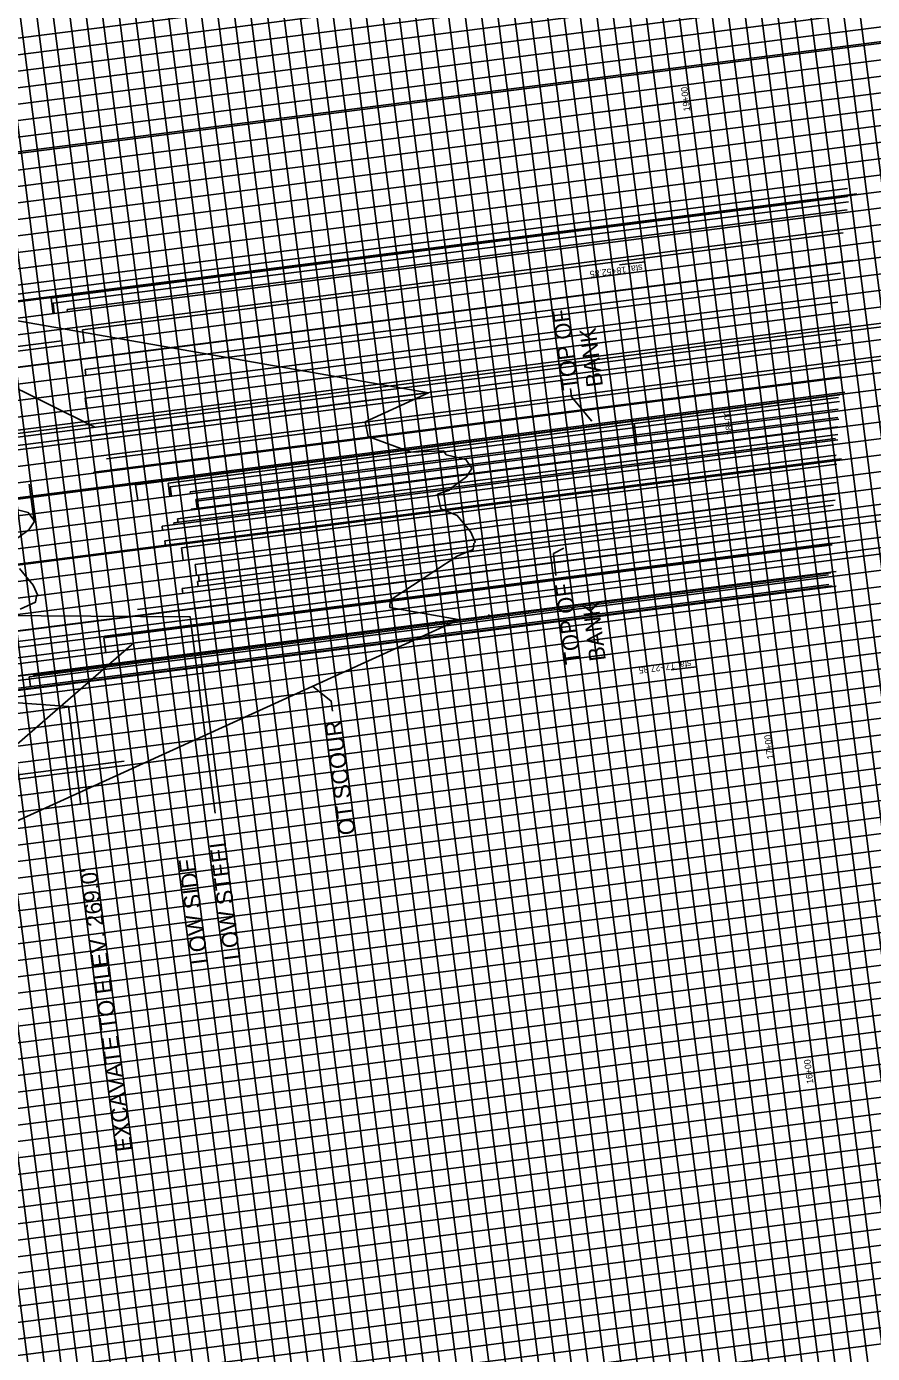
# Model space of a CAD drawing. Extents: x 2166991 to 2168413, y 842679 to 844296.
# Drawn here: x 2167837.4 to 2168096.3, y 843150.5 to 843556.7 of the extents above; entities that cross this region are included whole.
import ezdxf

# ---------------------------------------------------------------- set-up
doc = ezdxf.new("R2010")
doc.units = 0
for name, color, linetype in [('Exist Vertical Profile Ground Line', 7, 'Continuous'), ('Old_Level_46', 7, 'Continuous'), ('Prop Drainage Structure Bridge', 7, 'Continuous'), ('Prop Hydrographic Scour Overtopping', 7, 'Continuous'), ('Prop Plan Preparation Drainage Notes Label', 7, 'Continuous'), ('Prop Plan Preparation Sheet Bridge Report Limited Study CELL', 7, 'Continuous'), ('Scratch_Level_2', 7, 'Continuous'), ('Scratch_Level_3', 7, 'Continuous'), ('Scratch_Level_4', 7, 'Continuous'), ('Scratch_Level_8', 7, 'Continuous'), ('Scratch_Level_9', 7, 'Continuous')]:
    doc.layers.add(name, color=color, linetype=linetype)

msp = doc.modelspace()

# ---------------------------------------------------------------- linework, layer by layer
at = {"layer": 'Exist Vertical Profile Ground Line'}
for points in [[(2167834.04, 843399.62), (2167838.15, 843402.55), (2167839.75, 843405.06), (2167839.63, 843405.57), (2167837.93, 843407.87), (2167831.79, 843409.39)], [(2167835.45, 843378.32), (2167840.17, 843380.47), (2167840.43, 843382.37), (2167840.86, 843382.52), (2167839.45, 843385.69), (2167835.28, 843390.74)]]:
    msp.add_lwpolyline(points, dxfattribs=at)
at = {"layer": 'Old_Level_46'}
msp.add_line((2168024.22, 843428.68), (2168023.37, 843435.3), dxfattribs=at)
for points in [[(2168003.85, 843445.87), (2168004.17, 843443.36), (2168010.37, 843435.83)], [(2168001.8, 843397), (2167998.64, 843395.31), (2167999.43, 843388.63)], [(2167931.04, 843347.13), (2167930.65, 843350.18), (2167924.9, 843354.74)]]:
    msp.add_lwpolyline(points, dxfattribs=at)
at = {"layer": 'Prop Drainage Structure Bridge'}
for p, q in [((2167794.54, 843453.55), (2167848.25, 843460.41)), ((2167765.91, 843419.65), (2167960.44, 843444.5)), ((2167768.38, 843349.4), (2167969.63, 843375.1)), ((2167821.41, 843325.93), (2167864.73, 843331.46)), ((2167848.71, 843329.41), (2167867.3, 843331.79))]:
    msp.add_line(p, q, dxfattribs=at)
at = {"layer": 'Prop Hydrographic Scour Overtopping'}
for p, q in [((2167960.44, 843444.56), (2167801.84, 843472.35)), ((2167960.44, 843444.5), (2167941.02, 843435.65)), ((2167839.73, 843405.14), (2167838.27, 843416.61)), ((2167969.55, 843375.15), (2167948.63, 843378.82)), ((2167969.56, 843375.09), (2167815.18, 843304.73)), ((2167963.34, 843374.3), (2167962.46, 843374.35))]:
    msp.add_line(p, q, dxfattribs=at)
for points in [[(2167948.63, 843378.82), (2167948.71, 843381.1), (2167969.2, 843394.49), (2167974.08, 843396.56), (2167974.3, 843398.45), (2167974.74, 843398.81), (2167973.35, 843401.92), (2167969.17, 843406.97), (2167964.22, 843409.05), (2167963.2, 843413.51), (2167966.87, 843414.7), (2167967.84, 843415.74), (2167972.1, 843418.87), (2167973.54, 843421.14), (2167973.6, 843421.6), (2167971.82, 843424.1), (2167965.87, 843425.58), (2167965.04, 843426.75), (2167955.02, 843426.33), (2167942.01, 843431.12), (2167941.02, 843435.65)], [(2167978.91, 843376.29), (2167978.87, 843376.63)], [(2167915.33, 843361.79), (2167914.99, 843361.71)]]:
    msp.add_lwpolyline(points, dxfattribs=at)
at = {"layer": 'Prop Plan Preparation Drainage Notes Label'}
for points in [[(2167895.15, 843315.83), (2167893.14, 843331.53), (2167887.44, 843375.99), (2167781.12, 843376.66)], [(2167854.04, 843318.38), (2167850.29, 843348.53), (2167813.82, 843351.12)]]:
    msp.add_lwpolyline(points, dxfattribs=at)
at = {"layer": 'Prop Plan Preparation Sheet Bridge Report Limited Study CELL'}
for p, q in [((2168181.94, 842821.17), (2168023.56, 844061.1)), ((2168132.34, 842814.84), (2167973.96, 844054.76)), ((2168082.74, 842808.5), (2167924.37, 844048.43)), ((2168033.15, 842802.17), (2167874.77, 844042.09)), ((2167983.55, 842795.83), (2167825.17, 844035.76)), ((2168168.85, 842844.7), (2168016.81, 844035.03)), ((2168173.81, 842845.34), (2168021.77, 844035.67)), ((2168183.73, 842846.6), (2168031.69, 844036.93)), ((2168134.13, 842840.27), (2167982.09, 844030.6)), ((2168139.09, 842840.9), (2167987.05, 844031.23)), ((2168144.05, 842841.54), (2167992.01, 844031.86)), ((2168149.01, 842842.17), (2167996.97, 844032.5)), ((2168153.97, 842842.8), (2168001.93, 844033.13)), ((2168158.93, 842843.44), (2168006.89, 844033.77)), ((2168163.89, 842844.07), (2168011.85, 844034.4)), ((2167933.95, 842789.5), (2167775.57, 844029.42)), ((2168104.37, 842836.47), (2167952.33, 844026.8)), ((2168109.33, 842837.1), (2167957.29, 844027.43)), ((2168114.29, 842837.73), (2167962.25, 844028.06)), ((2168119.25, 842838.37), (2167967.21, 844028.7)), ((2168124.21, 842839), (2167972.17, 844029.33)), ((2167884.35, 842783.16), (2167725.98, 844023.09)), ((2168074.61, 842832.67), (2167922.57, 844023)), ((2168084.53, 842833.93), (2167932.49, 844024.26)), ((2168089.49, 842834.57), (2167937.45, 844024.9)), ((2168094.45, 842835.2), (2167942.41, 844025.53)), ((2168099.41, 842835.83), (2167947.37, 844026.16)), ((2168039.9, 842828.23), (2167887.86, 844018.56)), ((2168044.86, 842828.87), (2167892.82, 844019.19)), ((2168049.82, 842829.5), (2167897.78, 844019.83)), ((2168054.78, 842830.13), (2167902.74, 844020.46)), ((2168059.74, 842830.77), (2167907.69, 844021.1)), ((2168064.7, 842831.4), (2167912.65, 844021.73)), ((2168069.66, 842832.03), (2167917.61, 844022.36)), ((2168010.14, 842824.43), (2167858.1, 844014.76)), ((2168015.1, 842825.06), (2167863.06, 844015.39)), ((2168020.06, 842825.7), (2167868.02, 844016.03)), ((2168025.02, 842826.33), (2167872.98, 844016.66)), ((2168034.94, 842827.6), (2167882.9, 844017.93)), ((2167975.42, 842820), (2167823.38, 844010.33)), ((2167985.34, 842821.26), (2167833.3, 844011.59)), ((2167990.3, 842821.9), (2167838.26, 844012.23)), ((2167995.26, 842822.53), (2167843.22, 844012.86)), ((2168000.22, 842823.16), (2167848.18, 844013.49)), ((2168005.18, 842823.8), (2167853.14, 844014.13)), ((2167945.66, 842816.2), (2167793.62, 844006.52)), ((2167950.62, 842816.83), (2167798.58, 844007.16)), ((2167955.58, 842817.46), (2167803.54, 844007.79)), ((2167960.54, 842818.1), (2167808.5, 844008.43)), ((2167965.5, 842818.73), (2167813.46, 844009.06)), ((2167970.46, 842819.36), (2167818.42, 844009.69)), ((2167910.94, 842811.76), (2167758.9, 844002.09)), ((2167915.9, 842812.39), (2167763.86, 844002.72)), ((2167920.86, 842813.03), (2167768.82, 844003.36)), ((2167925.82, 842813.66), (2167773.78, 844003.99)), ((2167935.74, 842814.93), (2167783.7, 844005.26)), ((2167940.7, 842815.56), (2167788.66, 844005.89)), ((2167886.15, 842808.59), (2167734.11, 843998.92)), ((2167891.11, 842809.23), (2167739.06, 843999.56)), ((2167896.07, 842809.86), (2167744.02, 844000.19)), ((2167901.03, 842810.49), (2167748.98, 844000.82)), ((2167905.98, 842811.13), (2167753.94, 844001.46)), ((2168133.97, 843591.3), (2167638, 843527.95)), ((2168134.61, 843586.34), (2167638.64, 843522.99)), ((2168135.24, 843581.38), (2167639.27, 843518.03)), ((2168135.87, 843576.42), (2167639.9, 843513.07)), ((2168136.51, 843571.46), (2167640.54, 843508.11)), ((2168137.14, 843566.5), (2167641.17, 843503.15)), ((2168137.77, 843561.54), (2167641.8, 843498.19)), ((2168138.41, 843556.58), (2167642.44, 843493.23)), ((2168139.04, 843551.62), (2167643.07, 843488.27)), ((2168139.68, 843546.66), (2167618.91, 843480.15)), ((2168140.31, 843541.7), (2167644.34, 843478.35)), ((2168140.94, 843536.74), (2167644.97, 843473.39)), ((2168141.58, 843531.78), (2167645.61, 843468.43)), ((2168142.21, 843526.83), (2167646.24, 843463.47)), ((2168142.84, 843521.87), (2167646.87, 843458.52)), ((2168143.48, 843516.91), (2167647.51, 843453.56)), ((2168144.11, 843511.95), (2167648.14, 843448.6)), ((2168144.74, 843506.99), (2167648.77, 843443.64)), ((2168145.38, 843502.03), (2167649.41, 843438.68)), ((2168146.01, 843497.07), (2167625.24, 843430.55)), ((2168146.64, 843492.11), (2167650.67, 843428.76)), ((2168147.28, 843487.15), (2167651.31, 843423.8)), ((2168147.91, 843482.19), (2167651.94, 843418.84)), ((2168148.54, 843477.23), (2167652.57, 843413.88)), ((2168149.18, 843472.27), (2167653.21, 843408.92)), ((2168149.81, 843467.31), (2167653.84, 843403.96)), ((2168150.44, 843462.35), (2167654.47, 843399)), ((2168151.08, 843457.39), (2167655.11, 843394.04)), ((2168151.71, 843452.43), (2167655.74, 843389.08)), ((2168152.35, 843447.47), (2167631.58, 843380.95)), ((2168152.98, 843442.51), (2167657.01, 843379.16)), ((2168153.61, 843437.55), (2167657.64, 843374.2)), ((2168154.25, 843432.59), (2167658.28, 843369.24)), ((2168154.88, 843427.63), (2167658.91, 843364.28)), ((2168155.51, 843422.67), (2167659.54, 843359.32)), ((2168156.15, 843417.71), (2167660.18, 843354.36)), ((2168156.78, 843412.75), (2167660.81, 843349.4)), ((2168157.41, 843407.79), (2167661.44, 843344.44)), ((2168158.05, 843402.83), (2167662.08, 843339.48)), ((2168158.68, 843397.87), (2167637.91, 843331.35)), ((2168159.31, 843392.91), (2167663.34, 843329.56)), ((2168159.95, 843387.95), (2167663.98, 843324.6)), ((2168160.58, 843382.99), (2167664.61, 843319.64)), ((2168161.21, 843378.03), (2167665.24, 843314.68)), ((2168161.85, 843373.07), (2167665.88, 843309.72)), ((2168162.48, 843368.11), (2167666.51, 843304.76)), ((2168163.11, 843363.15), (2167667.14, 843299.8)), ((2168163.75, 843358.2), (2167667.78, 843294.84)), ((2168164.38, 843353.24), (2167668.41, 843289.89)), ((2168165.02, 843348.28), (2167644.25, 843281.76)), ((2168165.65, 843343.32), (2167669.68, 843279.97)), ((2168166.28, 843338.36), (2167670.31, 843275.01)), ((2168166.92, 843333.4), (2167670.95, 843270.05)), ((2168167.55, 843328.44), (2167671.58, 843265.09)), ((2168168.18, 843323.48), (2167672.21, 843260.13)), ((2168168.82, 843318.52), (2167672.85, 843255.17)), ((2168169.45, 843313.56), (2167673.48, 843250.21)), ((2168170.08, 843308.6), (2167674.11, 843245.25)), ((2168170.72, 843303.64), (2167674.75, 843240.29)), ((2168171.35, 843298.68), (2167650.58, 843232.16)), ((2168171.98, 843293.72), (2167676.01, 843230.37)), ((2168172.62, 843288.76), (2167676.65, 843225.41)), ((2168173.25, 843283.8), (2167677.28, 843220.45)), ((2168173.88, 843278.84), (2167677.91, 843215.49)), ((2168174.52, 843273.88), (2167678.55, 843210.53)), ((2168175.15, 843268.92), (2167679.18, 843205.57)), ((2168175.78, 843263.96), (2167679.81, 843200.61)), ((2168176.42, 843259), (2167680.45, 843195.65)), ((2168177.05, 843254.04), (2167681.08, 843190.69)), ((2168177.69, 843249.08), (2167656.92, 843182.56)), ((2168178.32, 843244.12), (2167682.35, 843180.77)), ((2168178.95, 843239.16), (2167682.98, 843175.81)), ((2168179.59, 843234.2), (2167683.62, 843170.85)), ((2168180.22, 843229.24), (2167684.25, 843165.89)), ((2168180.85, 843224.28), (2167684.88, 843160.93)), ((2168181.49, 843219.32), (2167685.52, 843155.97)), ((2168182.12, 843214.36), (2167686.15, 843151.01)), ((2168182.75, 843209.4), (2167686.78, 843146.05)), ((2168183.39, 843204.44), (2167687.42, 843141.09)), ((2168184.02, 843199.48), (2167663.25, 843132.97)), ((2168184.65, 843194.53), (2167688.68, 843131.17)), ((2168185.29, 843189.57), (2167689.32, 843126.21)), ((2168185.92, 843184.61), (2167689.95, 843121.26)), ((2168186.55, 843179.65), (2167690.58, 843116.3)), ((2168187.19, 843174.69), (2167691.22, 843111.34)), ((2168187.82, 843169.73), (2167691.85, 843106.38)), ((2168188.45, 843164.77), (2167692.48, 843101.42))]:
    msp.add_line(p, q, dxfattribs=at)
at = {"layer": 'Scratch_Level_2'}
msp.add_line((2168101.65, 843552.42), (2167744.64, 843506.82), dxfattribs=at)
at = {"layer": 'Scratch_Level_3'}
for p, q in [((2167815.39, 843428.51), (2168411.81, 843504.69)), ((2167861.89, 843424.37), (2168413.08, 843494.78)), ((2167858.33, 843434), (2167813.96, 843456.03)), ((2167871.33, 843378.22), (2168277.38, 843430.09)), ((2167817.84, 843361.31), (2168278.64, 843420.17)), ((2167870.26, 843368), (2167818.59, 843323.14))]:
    msp.add_line(p, q, dxfattribs=at)
at = {"layer": 'Scratch_Level_4'}
for p, q in [((2168088.64, 843507.14), (2167815.29, 843472.22)), ((2168088.67, 843504.62), (2167844.97, 843473.49)), ((2168088.99, 843503.04), (2167845.52, 843471.94)), ((2168088.56, 843500.54), (2167849.85, 843470.04)), ((2168087.31, 843493.51), (2167854.58, 843463.78)), ((2168086.48, 843481.16), (2167855.37, 843451.64)), ((2167845.57, 843468.77), (2167844.97, 843473.49)), ((2167845.92, 843468.82), (2167845.52, 843471.94)), ((2167849.94, 843469.33), (2167849.85, 843470.04)), ((2168085.73, 843472.3), (2167855.38, 843442.88)), ((2167855.07, 843459.91), (2167854.58, 843463.78)), ((2168086.66, 843460.73), (2167855.42, 843431.19)), ((2167855.6, 843449.89), (2167855.37, 843451.64)), ((2168086.56, 843449.42), (2167857.98, 843420.22)), ((2167855.77, 843439.83), (2167855.38, 843442.88)), ((2168086.26, 843443.93), (2167870.81, 843416.41)), ((2168085.95, 843443.06), (2167880.74, 843416.85)), ((2168086.24, 843441.89), (2167881.38, 843415.73)), ((2168085.76, 843439.53), (2167887.53, 843414.21)), ((2168085.66, 843434.17), (2167887.75, 843408.89)), ((2168085.72, 843437.01), (2167889.23, 843411.91)), ((2168086, 843436.52), (2167889.35, 843411.4)), ((2167855.43, 843431.08), (2167855.42, 843431.19)), ((2168085.72, 843430.12), (2167878.89, 843403.7)), ((2168085.01, 843430.58), (2167882.49, 843404.72)), ((2168085.67, 843431.76), (2167883.64, 843405.95)), ((2168085.22, 843425.45), (2167879.76, 843399.21)), ((2168085.6, 843424.18), (2167882.56, 843398.25)), ((2168085.36, 843422.68), (2167884.87, 843397.07)), ((2167858.01, 843419.96), (2167857.98, 843420.22)), ((2167871.43, 843411.59), (2167870.81, 843416.41)), ((2167881.25, 843412.84), (2167880.74, 843416.85)), ((2167881.74, 843412.91), (2167881.38, 843415.73)), ((2167887.6, 843413.65), (2167887.53, 843414.21)), ((2168085.27, 843417.09), (2167889.05, 843392.03)), ((2168085.04, 843413.62), (2167890.03, 843388.71)), ((2168084.94, 843413.7), (2167890.46, 843388.86)), ((2168084.37, 843410.11), (2167885.05, 843384.65)), ((2167889.3, 843411.39), (2167889.23, 843411.91)), ((2167889.64, 843409.13), (2167889.35, 843411.4)), ((2168084.85, 843411.72), (2167889.77, 843386.8)), ((2167883.78, 843404.88), (2167883.64, 843405.95)), ((2167887.78, 843408.64), (2167887.75, 843408.89)), ((2167879.04, 843402.48), (2167878.89, 843403.7)), ((2167882.56, 843404.17), (2167882.49, 843404.72)), ((2168083.92, 843398.03), (2167861.12, 843369.57)), ((2168083.92, 843398.49), (2167861.36, 843370.07)), ((2167879.97, 843397.56), (2167879.76, 843399.21)), ((2167882.6, 843397.89), (2167882.56, 843398.25)), ((2167885.37, 843393.21), (2167884.87, 843397.07)), ((2168082.84, 843388.87), (2167838.25, 843357.63)), ((2168083.55, 843389.39), (2167839.68, 843358.24)), ((2167889.47, 843388.69), (2167889.05, 843392.03)), ((2167890.26, 843386.87), (2167890.03, 843388.71)), ((2167890.47, 843388.77), (2167890.46, 843388.86)), ((2168083.95, 843385.46), (2167834.18, 843353.55)), ((2168082.98, 843385.82), (2167834.96, 843354.14)), ((2167885.25, 843383.11), (2167885.05, 843384.65)), ((2167889.96, 843385.28), (2167889.77, 843386.8)), ((2167861.7, 843364.98), (2167861.12, 843369.57)), ((2167861.42, 843369.6), (2167861.36, 843370.07)), ((2167838.63, 843354.61), (2167838.25, 843357.63)), ((2167839.73, 843357.82), (2167839.68, 843358.24))]:
    msp.add_line(p, q, dxfattribs=at)
at = {"layer": 'Scratch_Level_8'}
for p, q in [((2168091.54, 843505.51), (2167796.91, 843467.87)), ((2168090.16, 843485.03), (2167799.4, 843447.89)), ((2168089.2, 843465.59), (2167801.33, 843428.82)), ((2168087.87, 843444.75), (2167804.17, 843408.52)), ((2168086.81, 843424.32), (2167806.08, 843388.46)), ((2168086.26, 843403.82), (2167808.5, 843368.34)), ((2168086.42, 843400.54), (2167809.11, 843365.12)), ((2168085.19, 843389.79), (2167809.7, 843354.6)), ((2168085.19, 843385.4), (2167810.15, 843350.27))]:
    msp.add_line(p, q, dxfattribs=at)
at = {"layer": 'Scratch_Level_9'}
for p, q in [((2168040.48, 843533.98), (2168012.93, 843530.47)), ((2168026.62, 843484.68), (2168018.91, 843483.7)), ((2168053.15, 843434.79), (2168025.6, 843431.27)), ((2168042.46, 843360.69), (2168034.74, 843359.7)), ((2168065.82, 843335.6), (2168038.27, 843332.08)), ((2168078.49, 843236.4), (2168050.94, 843232.88))]:
    msp.add_line(p, q, dxfattribs=at)

# ---------------------------------------------------------------- texts
at = {"layer": 'Old_Level_46'}
for s, p in [('TOP OF', (2168006.4, 843445.69)), ('BANK', (2168013.84, 843446.64)), ('TOP OF', (2168007.27, 843361.78)), ('BANK', (2168014.71, 843362.73)), ('OT SCOUR', (2167938.1, 843309.47))]:
    msp.add_text(s, height=5, rotation=97.279, dxfattribs=at).set_placement(p)
at = {"layer": 'Prop Plan Preparation Drainage Notes Label'}
for s, p in [('LOW STEEL', (2167902.96, 843271.21)), ('LOW SIDE', (2167893.04, 843269.94)), ("EXCAVATE TO ELEV. 269.0'", (2167869.83, 843212.58))]:
    msp.add_text(s, height=5, rotation=97.279, dxfattribs=at).set_placement(p)
at = {"layer": 'Scratch_Level_9'}
for s, rotation, p in [('19+00', 97.279, (2168040.54, 843530.87)), ('sta. 18+52.85', 187.279, (2168025.82, 843483.86)), ('18+00', 97.279, (2168053.64, 843431.72)), ('sta. 17+27.85', 187.279, (2168040.78, 843362.61)), ('17+00', 97.279, (2168066.06, 843332.5)), ('16+00', 97.279, (2168078.22, 843233.14))]:
    msp.add_text(s, height=2, rotation=rotation, dxfattribs=at).set_placement(p)

doc.saveas('drawing.dxf')
